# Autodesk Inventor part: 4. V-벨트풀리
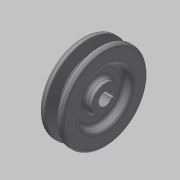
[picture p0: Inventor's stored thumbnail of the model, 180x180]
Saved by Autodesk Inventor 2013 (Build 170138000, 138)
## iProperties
Created: 2015-02
Part Number: 4. V-벨트풀리
Material: 일반
Document SubType Name: Modeling
Designer: Administrator
Density: 1 g/cm^3
Author: Administrator
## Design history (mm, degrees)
sketch "스케치1"
  geometry: L1 (-12.5, 0)-(12.5, 0); L2 (-12.5, 11)-(-6.5, 11); L3 (-6.5, 11)-(-6.5, 21.5); L4 (-6.5, 21.5)-(-12.5, 21.5); L5 (-12.5, 21.5)-(-12.5, 35.2); L6 (-12.5, 35.2)-(-7.825, 35.2); L7 (-7.825, 35.2)-(-5.074, 26.2); L8 (-5.074, 26.2)-(-0.926, 26.2); L9 (-0.926, 26.2)-(1.825, 35.2); L10 (1.825, 35.2)-(6.5, 35.2); L11 (6.5, 35.2)-(6.5, 21.5); L12 (6.5, 21.5)-(0.5, 21.5); L13 (0.5, 21.5)-(0.5, 11); L14 (0.5, 11)-(12.5, 11); L15 (-7, 32.5)-(1, 32.5); L16 (-12.5, 11)-(-12.5, 5.5); L17 (-12.5, 5.5)-(12.5, 5.5); L18 (12.5, 5.5)-(12.5, 11); 4 further points
  constraints: 36 end point, 6 parallel, 4 equal length, 3 collinear, 3 midpoint, 3 vertical alignment, 2 perpendicular, 2 point on line, 2 vertical, 1 coincident, 1 horizontal
  dimensions: "d0" = 25 distance of L1.start L1.end; "d2" = 6.3 distance between parallel lines of L15 L8; "d3" = 34 deg angle of L9 L7; "d4" = 19 distance between parallel lines of L5 L11; "d5" = 65 diameter of L15 L1; "d6" = 2.7 distance between parallel lines of L10 L15; "d7" = 6 distance between parallel lines of L5 L3; "d8" = 43 diameter of L4 L1; "d9" = 22 diameter of L14 L1; "d10" = 11 diameter of L17 L1; "d12" = 8 distance of L15.start L15.end
revolve "회전1" sketch "스케치1" stored, may be unused: angle "d13" = 90 deg
fillet "모깎기1" dims "d14" = 1, "d15" = 0.5, "d16" = 2
fillet "모깎기2" dims "d17" = 3
sketch "스케치2"
  geometry: L1 (-2, 7.3)-(2, 7.3); L2 (0, 7.3)-(0, -5.5); L3 (-2, 7.3)-(-2, 5.123); L4 (2, 7.3)-(2, 5.123); L5 (2, 5.123)-(-2, 5.123); A1 r 5.5 centre (0, 0) between (0, -5.5) and (-2, 5.123) reference
  constraints: 10 end point, 3 point on circle, 2 perpendicular, 1 horizontal, 1 midpoint, 1 parallel, 1 vertical alignment
  dimensions: "d18" = 12.8 distance of L2.start L2.end; "d20" = 4 distance of L1.start L1.end
extrude "돌출1" cut sketch "스케치2" stored distance "d21" = 10; taper "d22" = 0 deg
node "솔리드1"
